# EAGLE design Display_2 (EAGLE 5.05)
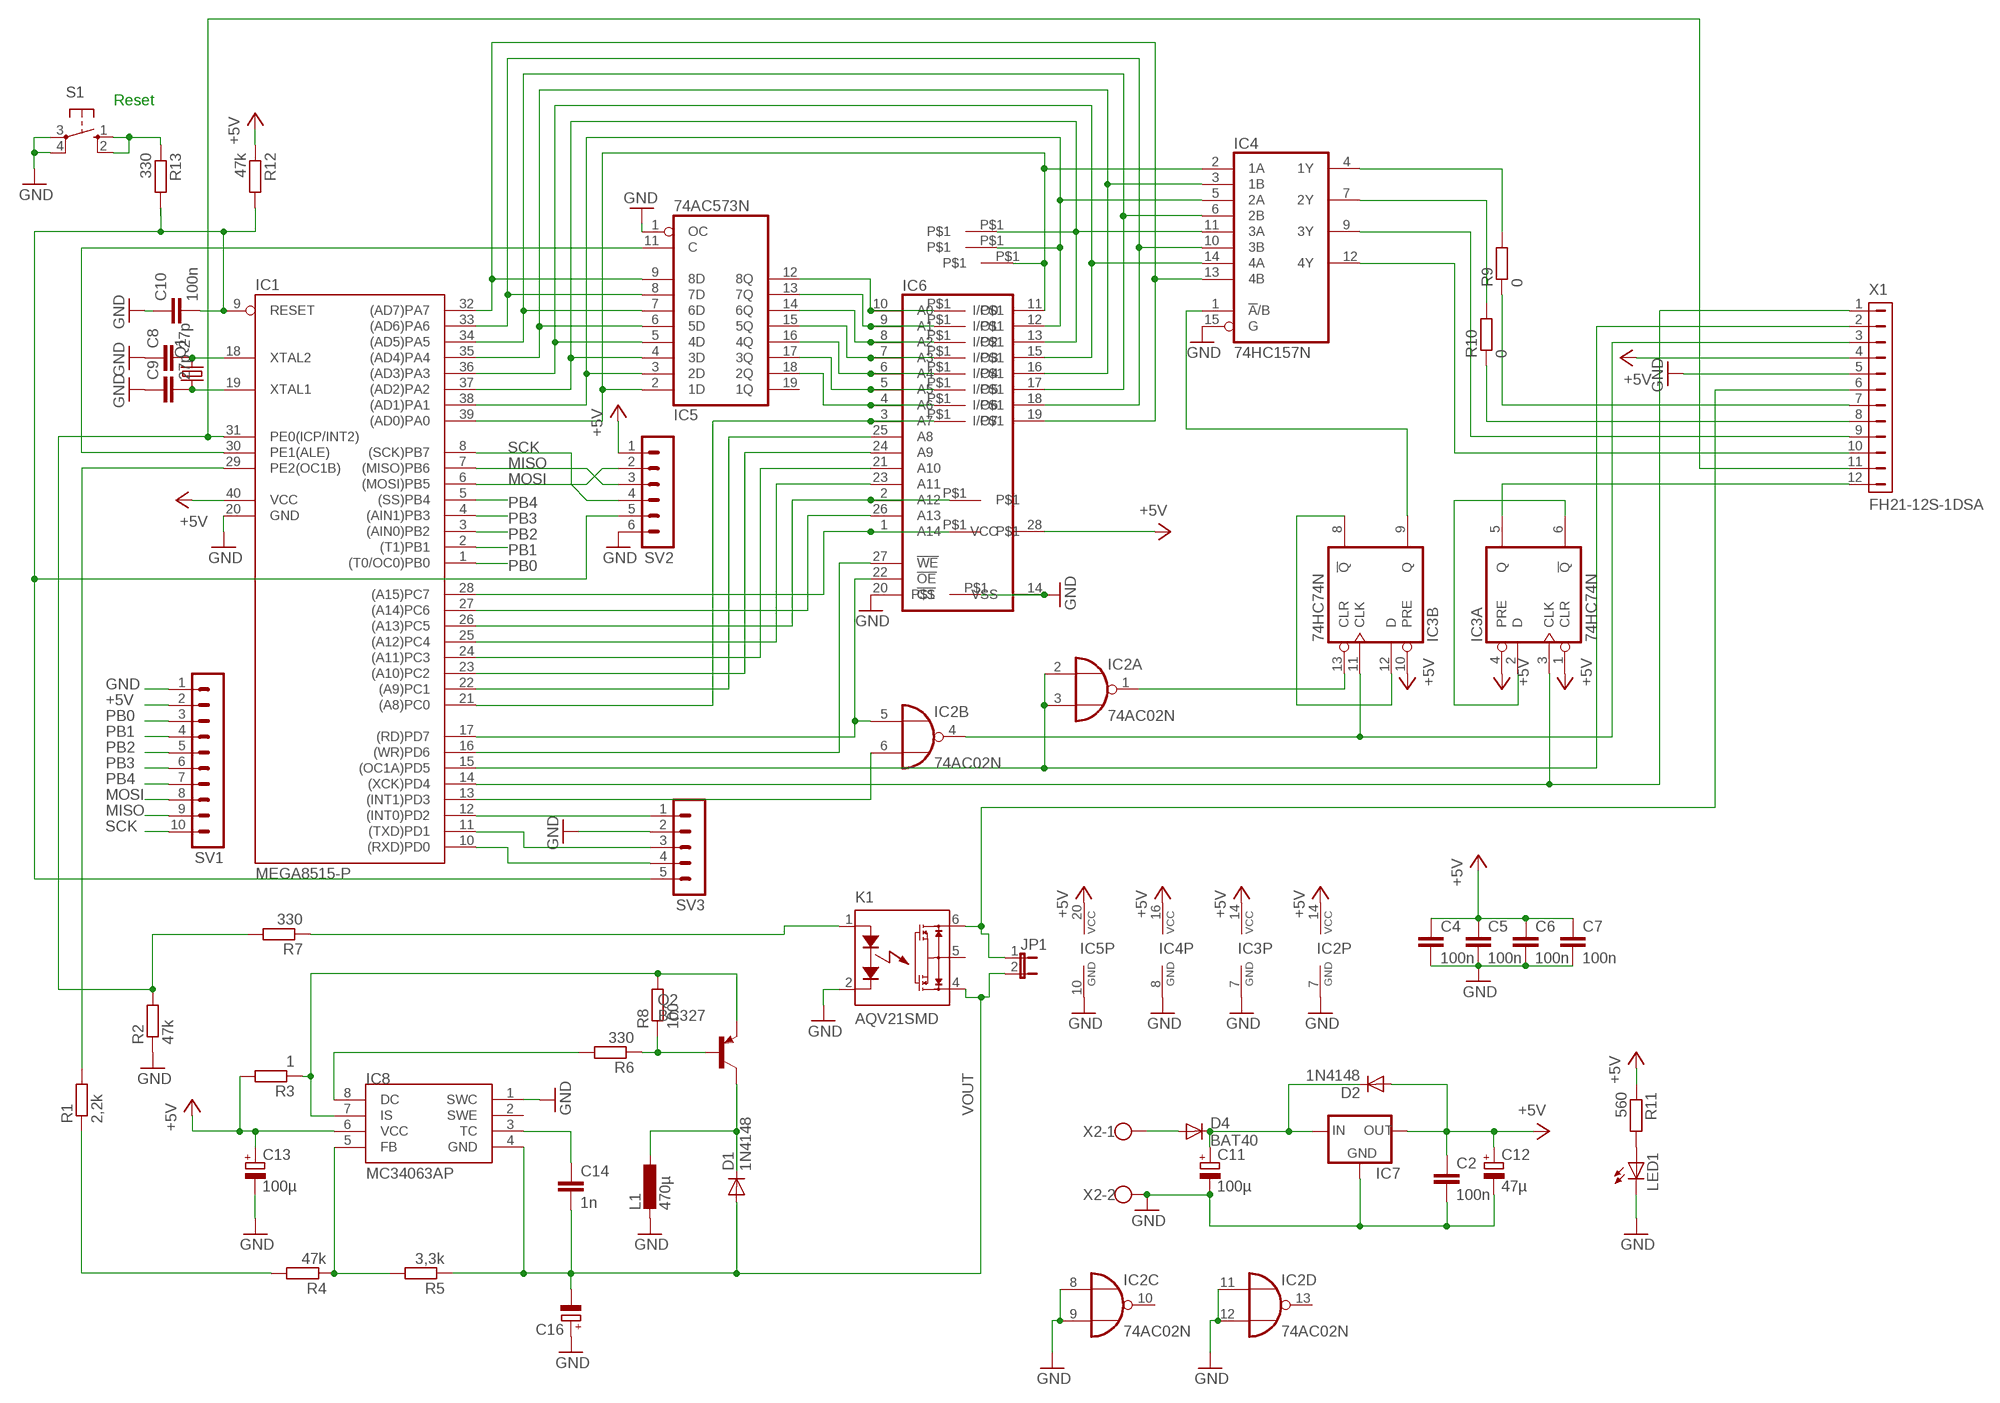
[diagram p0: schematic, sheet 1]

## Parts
C2  100n  C-EUC1206  [C1206]
C4  100n  C-EUC1206  [C1206]
C5  100n  C-EUC1206  [C1206]
C6  100n  C-EUC1206  [C1206]
C7  100n  C-EUC1206  [C1206]
C8  27p  C-EUC1206  [C1206]
C9  27p  C-EUC1206  [C1206]
C10  100n  C-EUC1206  [C1206]
C11  100µ  CPOL-EUE5-5  [E5-5]
C12  47µ  CPOL-EUE5-5  [E5-5]
C13  100µ  CPOL-EUE5-5  [E5-5]
C14  1n  C-EUC1206  [C1206]
C16  CPOL-EUE5-5  [E5-5]
D1  1N4148  DIODE-D-2.5  [D-2.5]
D2  1N4148  [DO35-10]
D4  BAT40  DIODE-D-2.5  [D-2.5]
IC1  MEGA8515-P  [DIL40]
IC2  74AC02N  [DIL14]
IC3  74HC74N  [DIL14]
IC4  74HC157N  [DIL16]
IC5  74AC573N  [DIL20]
IC6  62256P  [DIL28-6]
IC7  78XXS  [78XXS]
IC8  MC34063AP  [DIL08]
JP1  JP1E  [JP1]
K1  AQV21SMD  [DIL06SMD]
L1  470µ  L-EU0204/7  [0204/7]
LED1  LED3MM  [LED3MM]
Q1  CRYSTALHC49U-V  [HC49U-V]
Q2  BC327  [TO92]
R1  2,2k  R-EU_M1206  [M1206]
R2  47k  R-EU_M1206  [M1206]
R3  1  R-EU_M1206  [M1206]
R4  47k  R-EU_M1206  [M1206]
R5  3,3k  R-EU_M1206  [M1206]
R6  330  R-EU_M1206  [M1206]
R7  330  R-EU_M1206  [M1206]
R8  100  R-EU_M1206  [M1206]
R9  0  R-EU_0207/10  [0207/10]
R10  0  R-EU_0207/10  [0207/10]
R11  560  R-EU_M1206  [M1206]
R12  47k  R-EU_M1206  [M1206]
R13  330  R-EU_M1206  [M1206]
S1  10-XX  [B3F-10XX]
SV1  MA10-1  [MA10-1]
SV2  MA06-1  [MA06-1]
SV3  MA05-1  [MA05-1]
U$2  PAD  [PAD]
U$3  PAD  [PAD]
U$4  PAD  [PAD]
U$5  PAD  [PAD]
U$6  PAD  [PAD]
U$7  PAD  [PAD]
U$8  PAD  [PAD]
U$9  PAD  [PAD]
U$10  PAD  [PAD]
U$11  PAD  [PAD]
U$12  PAD  [PAD]
U$13  PAD  [PAD]
U$14  PAD  [PAD]
U$15  PAD  [PAD]
X1  FH21-12S-1DSA  [FH21-12S-1DSA]
X2  W237-102  [W237-102]

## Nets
+5V [Power]: C2.1 C4.1 C5.1 C6.1 C7.1 C12.+ C13.+ D2.A IC1.40(VCC) IC2.14(P:VCC) IC3.1(A:CLR) IC3.4(A:PRE) IC3.10(B:PRE) IC3.14(P:VCC) IC4.16(VCC) IC5.20(VCC) IC6.28(VCC) IC7.OUT IC8.6(VCC) R3.2 R11.1 R12.1 SV1.2 SV2.1 X1.4
GND: C2.2 C4.2 C5.2 C6.2 C7.2 C8.1 C9.1 C10.1 C11.- C12.- C13.- C16.+ IC1.20(GND) IC2.7(P:GND) IC2.8(C:I0) IC2.9(C:I1) IC2.11(D:I0) IC2.12(D:I1) IC3.7(P:GND) IC4.8(GND) IC4.15(G) IC5.1(OC) IC5.10(GND) IC6.14(VSS) IC6.20(!CS) IC7.GND IC8.1(SWC) K1.2(K) L1.2 LED1.K(C) R2.1 S1.3(P) S1.4(P1) SV1.1 SV2.6 SV3.2 U$11.P$1 X1.5 X2.2
L1 [Power]: D1.C L1.1 Q2.3(C)
MISO: IC1.7((MISO)PB6) SV1.9 SV2.3
MOSI: IC1.6((MOSI)PB5) SV1.8 SV2.2
N$1: IC1.39((AD0)PA0) IC4.2(1A) IC5.2(1D) IC6.11(I/O0) U$15.P$1
N$2: IC1.38((AD1)PA1) IC4.5(2A) IC5.3(2D) IC6.12(I/O1) U$13.P$1
N$3: IC1.37((AD2)PA2) IC4.11(3A) IC5.4(3D) IC6.13(I/O2) U$8.P$1
N$4: IC1.36((AD3)PA3) IC4.14(4A) IC5.5(4D) IC6.15(I/O3)
N$5: IC1.35((AD4)PA4) IC4.3(1B) IC5.6(5D) IC6.16(I/O4)
N$6: IC1.34((AD5)PA5) IC4.6(2B) IC5.7(6D) IC6.17(I/O5)
N$7: IC1.33((AD6)PA6) IC4.10(3B) IC5.8(7D) IC6.18(I/O6)
N$8: IC1.32((AD7)PA7) IC4.13(4B) IC5.9(8D) IC6.19(I/O7)
N$9: IC5.12(8Q) IC6.10(A0) U$4.P$1
N$10: IC5.13(7Q) IC6.9(A1) U$5.P$1
N$11: IC5.14(6Q) IC6.8(A2) U$6.P$1
N$12: IC5.15(5Q) IC6.7(A3) U$12.P$1
N$13: IC5.16(4Q) IC6.6(A4) U$14.P$1
N$14: IC5.17(3Q) IC6.5(A5) U$7.P$1
N$15: IC5.18(2Q) IC6.4(A6) U$9.P$1
N$16: IC1.21((A8)PC0) IC6.3(A7) U$10.P$1
N$17: IC1.22((A9)PC1) IC6.25(A8)
N$18: IC1.23((A10)PC2) IC6.24(A9)
N$19: IC1.24((A11)PC3) IC6.21(A10)
N$20: IC1.25((A12)PC4) IC6.23(A11)
N$21: IC1.26((A13)PC5) IC6.2(A12) U$3.P$1
N$22: IC1.27((A14)PC6) IC6.26(A13)
N$23: IC1.28((A15)PC7) IC6.1(A14) U$2.P$1
N$24: IC1.16((WR)PD6) IC6.27(!WE)
N$25: IC1.17((RD)PD7) IC2.5(B:I0) IC6.22(!OE)
N$26: IC3.8(B:!Q) IC3.12(B:D)
N$27: IC3.9(B:Q) IC4.1(!A!/B)
N$28: IC3.2(A:D) IC3.6(A:!Q)
N$29: IC2.1(A:O) IC3.13(B:CLR)
N$31: IC1.13((INT1)PD3) IC2.6(B:I1)
N$32: C8.2 IC1.18(XTAL2) Q1.2
N$33: C9.2 IC1.19(XTAL1) Q1.1
N$34: R13.1 S1.1(S) S1.2(S1)
N$35: IC1.31(PE0(ICP/INT2)) R2.2 R7.2 X1.11
N$36: IC1.15((OC1A)PD5) IC2.2(A:I0) IC2.3(A:I1) X1.2
N$37: IC1.30(PE1(ALE)) IC5.11(C)
N$38: IC3.5(A:Q) X1.12
N$39: IC2.4(B:O) IC3.11(B:CLK) X1.3
N$40: R9.1 X1.7
N$41: R10.1 X1.8
N$42: IC4.9(3Y) X1.9
N$43: IC4.12(4Y) X1.10
N$45: C14.1 IC8.3(TC)
N$48: IC8.5(FB) R4.1 R5.2
N$49: K1.1(A) R7.1
N$50: LED1.A R11.2
N$51: R1.1 R4.2
N$52: IC1.29(PE2(OC1B)) R1.2
N$53: IC8.8(DC) R6.2
N$54: Q2.2(B) R6.1 R8.1
N$55: IC8.7(IS) Q2.1(E) R3.1 R8.2
N$57 [Power]: JP1.1 K1.6(D1) X1.6
N$58: IC4.4(1Y) R9.2
N$59: IC4.7(2Y) R10.2
N$60: D4.A X2.1
N$61: IC1.14((XCK)PD4) IC3.3(A:CLK) X1.1
N$63: IC1.12((INT0)PD2) SV3.1
PB0: IC1.1((T0/OC0)PB0) SV1.3
PB1: IC1.2((T1)PB1) SV1.4
PB2: IC1.3((AIN0)PB2) SV1.5
PB3: IC1.4((AIN1)PB3) SV1.6
PB4: IC1.5((SS)PB4) SV1.7
RESET: C10.2 IC1.9(RESET) R12.2 R13.2 SV2.5 SV3.5
RXD: IC1.10((RXD)PD0) SV3.4
SCK: IC1.8((SCK)PB7) SV1.10 SV2.4
TXD: IC1.11((TXD)PD1) SV3.3
VIN: C11.+ D2.C D4.C IC7.IN
VOUT [Power]: C14.2 C16.- D1.A IC8.4(GND) JP1.2 K1.4(D2) R5.1
Unconnected: IC2.10(C:O) IC2.13(D:O) IC5.19(1Q) IC8.2(SWE) K1.5(S)

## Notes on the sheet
- Reset

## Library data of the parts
C2 C4-C10 C14 = rcl:C-EU: CAPACITOR, European symbol
C11-C13 C16 = rcl:CPOL-EU: POLARIZED CAPACITOR, European symbol
D1 D4 = diode:DIODE-: DIODE
D2 = diode:1N4148: DIODE
IC1 = atmel:MEGA8515-P: MICROCONTROLLER 8 Kbytes FLASH 512 bytes SRAM 512 bytes EEPROM USART 8-channel 10 bit ADC Source: avr.lbr
IC2 = 74xx-eu:74*02: Quad 2-input NOR gate
IC3 = 74xx-eu:74*74: Dual D type positive edge triggered FLIP FLOP, preset and clear
IC4 = 74xx-eu:74*157: Quadruple 2-line to 1-line data SELECTOR/MULTIPLEXER
IC5 = 74xx-eu:74*573: 8-bit D latch BUS DRIVER
IC6 = memory-hitachi:62256P: MEMORY
IC7 = v-reg:78XXS: VOLTAGE REGULATOR
IC8 = mc34063:MC34063
JP1 = jumper:JP1E: JUMPER
K1 = relay:AQV*: PhotoMOS Relay NAiS Source: http://www.mew-europe.com/.. pti_en.pdf
L1 = rcl:L-EU: INDUCTOR, European symbol
LED1 = led:LED: LED
Q1 = crystal:CRYSTAL: CRYSTAL
Q2 = transistor-pnp:BC327: PNP Transistor
R1-R13 = rcl:R-EU_: RESISTOR, European symbol
S1 = switch-omron:10-XX: OMRON SWITCH
SV1 = con-lstb:MA10-1: PIN HEADER
SV2 = con-lstb:MA06-1: PIN HEADER
SV3 = con-lstb:MA05-1: PIN HEADER
U$2-U$15 = special-pad:PAD
X1 = con-hirose:FH21-12S-1DSA: FPC CONNECTOR Source: con-hirose.lbr from Bob Starr <rtzaudio@mindspring.com>
X2 = con-wago-500:W237-102: WAGO SCREW CLAMP

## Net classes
0 default: width 0.4 mm
1 Power: width 0.6 mm
2 Supply: width 1 mm

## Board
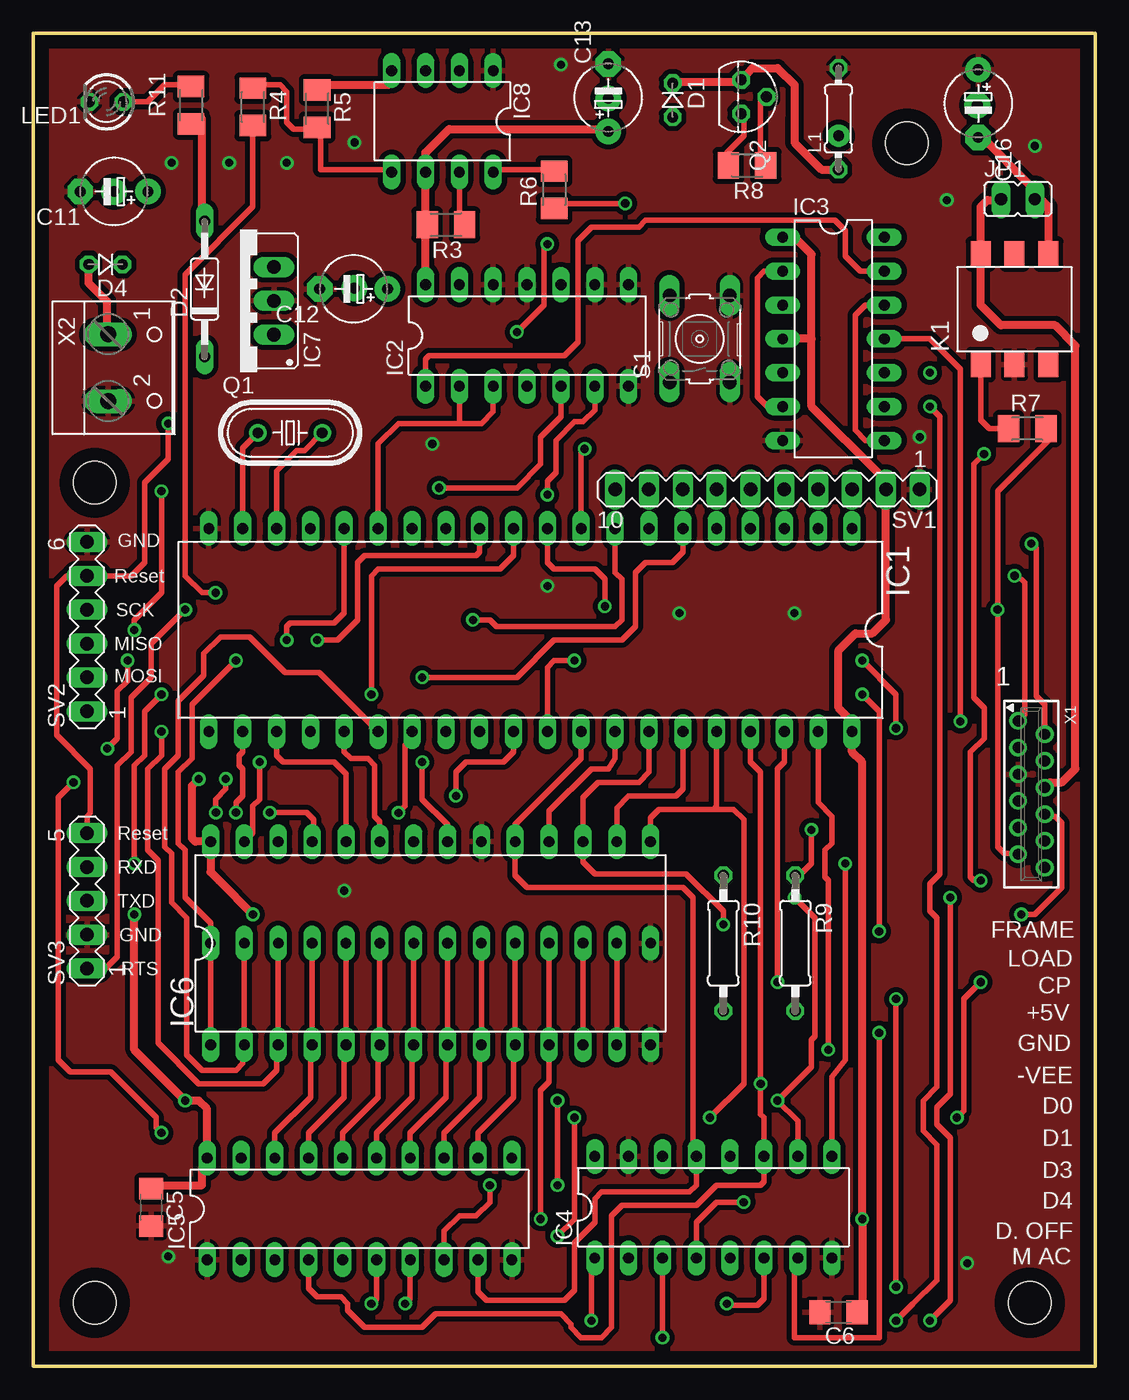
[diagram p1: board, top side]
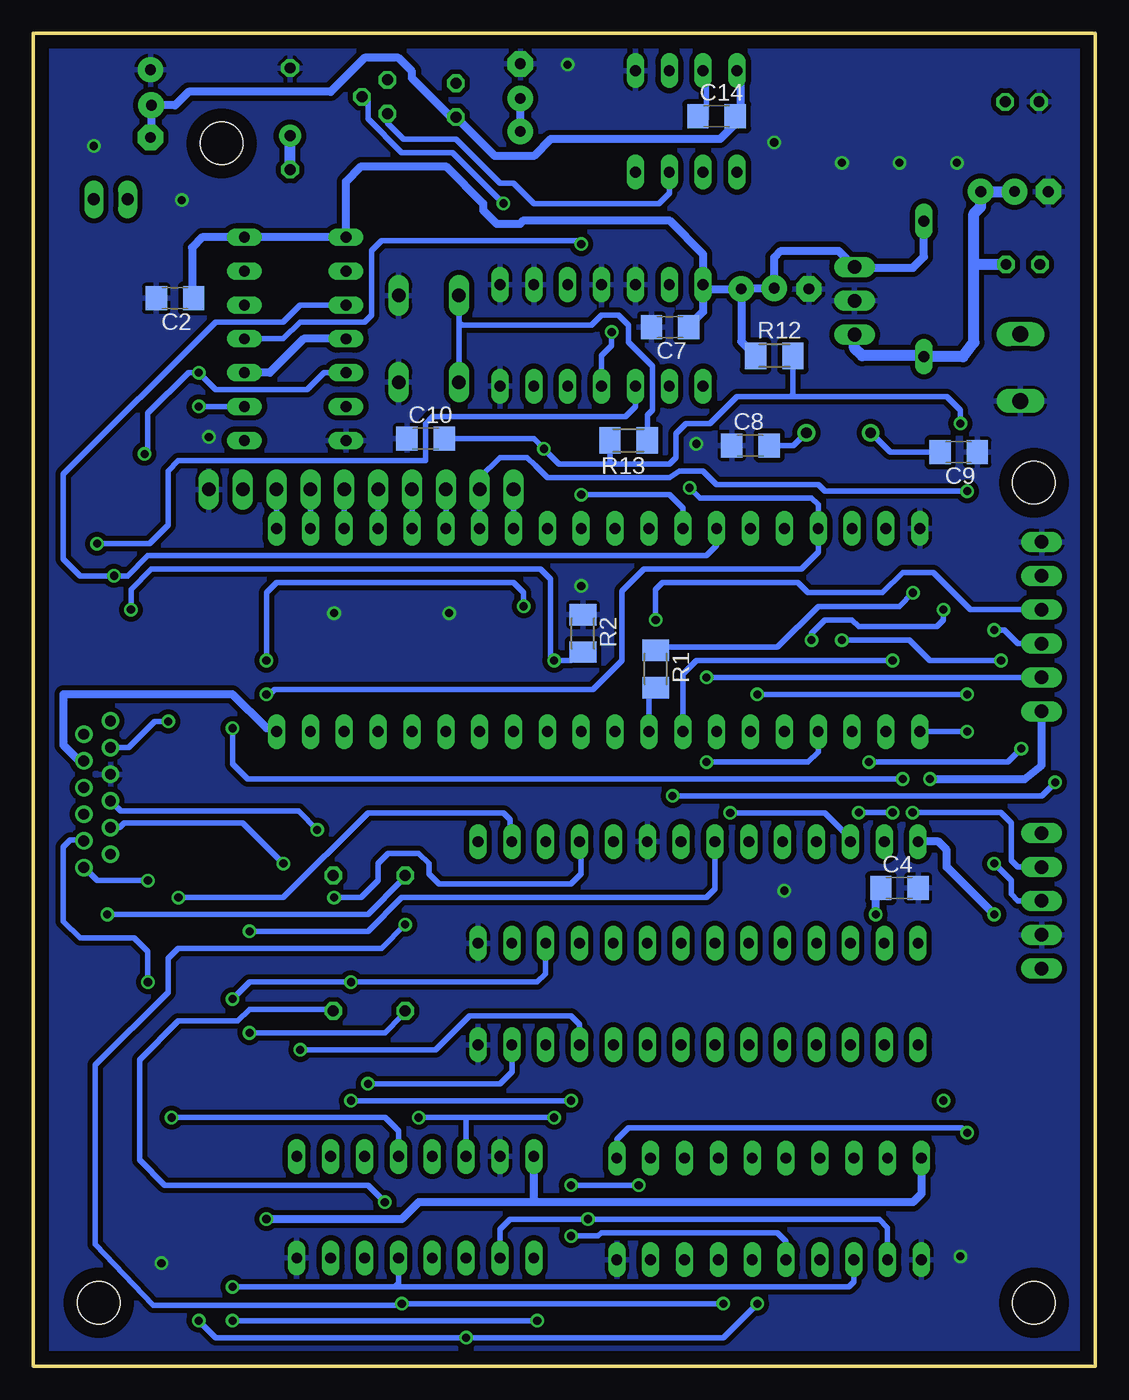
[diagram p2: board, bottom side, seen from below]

Size 79.68 x 100 mm. Coordinates in mm from the lower left corner, seen from the top.
Outline: 79.68,99.99 79.68,0 0,0 0,99.99
Outline: 0.15,100 79.53,100
Copper layers (1*16): Top 0.035mm / dielectric 1.5mm / Bottom 0.035mm
Design rules "Bilex_DRU_15mil": minimum track width 10mil, minimum drill 24mil, track to track 15mil, track to pad 15mil, pad to pad 15mil, via to via 15mil, smd to smd 10mil, copper to edge 40mil, drill to drill 8mil, minimum pad ring 10mil, minimum via ring 8mil, stop-mask expansion 4mil, vias tented up to drill 0mil, thermal gap 10mil
Holes 3.2 mm at 4.6,4.75 4.6,66.28 74.77,4.75 65.56,91.74

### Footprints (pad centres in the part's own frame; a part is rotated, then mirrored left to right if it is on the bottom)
C1206 = smd 1.6 x 1.8: 1 -1.4,0; 2 1.4,0
E5-5 = drill 0.813 pad 1.905 round: + -2.54,0 | drill 0.813 pad 1.905 octagon: - 2.54,0
D-2.5 = drill 0.813 octagon: A 1.27,0; C -1.27,0
DO35-10 = drill 0.813 long: A 5.08,0; C -5.08,0
DIL40 = drill 0.813 long: 1 -24.13,-7.62; 2 -21.59,-7.62; 3 -19.05,-7.62; 4 -16.51,-7.62; 5 -13.97,-7.62; 6 -11.43,-7.62; 7 -8.89,-7.62; 8 -6.35,-7.62; 9 -3.81,-7.62; 10 -1.27,-7.62; 11 1.27,-7.62; 12 3.81,-7.62; 13 6.35,-7.62; 14 8.89,-7.62; 15 11.43,-7.62; 16 13.97,-7.62; 17 16.51,-7.62; 18 19.05,-7.62; 19 21.59,-7.62; 20 24.13,-7.62; 21 24.13,7.62; 22 21.59,7.62; 23 19.05,7.62; 24 16.51,7.62; 25 13.97,7.62; 26 11.43,7.62; 27 8.89,7.62; 28 6.35,7.62; 29 3.81,7.62; 30 1.27,7.62; 31 -1.27,7.62; 32 -3.81,7.62; 33 -6.35,7.62; 34 -8.89,7.62; 35 -11.43,7.62; 36 -13.97,7.62; 37 -16.51,7.62; 38 -19.05,7.62; 39 -21.59,7.62; 40 -24.13,7.62
DIL14 = drill 0.813 long: 1 -7.62,-3.81; 2 -5.08,-3.81; 3 -2.54,-3.81; 4 0,-3.81; 5 2.54,-3.81; 6 5.08,-3.81; 7 7.62,-3.81; 8 7.62,3.81; 9 5.08,3.81; 10 2.54,3.81; 11 0,3.81; 12 -2.54,3.81; 13 -5.08,3.81; 14 -7.62,3.81
DIL16 = drill 0.813 long: 1 -8.89,-3.81; 2 -6.35,-3.81; 3 -3.81,-3.81; 4 -1.27,-3.81; 5 1.27,-3.81; 6 3.81,-3.81; 7 6.35,-3.81; 8 8.89,-3.81; 9 8.89,3.81; 10 6.35,3.81; 11 3.81,3.81; 12 1.27,3.81; 13 -1.27,3.81; 14 -3.81,3.81; 15 -6.35,3.81; 16 -8.89,3.81
DIL20 = drill 0.813 long: 1 -11.43,-3.81; 2 -8.89,-3.81; 3 -6.35,-3.81; 4 -3.81,-3.81; 5 -1.27,-3.81; 6 1.27,-3.81; 7 3.81,-3.81; 8 6.35,-3.81; 9 8.89,-3.81; 10 11.43,-3.81; 11 11.43,3.81; 12 8.89,3.81; 13 6.35,3.81; 14 3.81,3.81; 15 1.27,3.81; 16 -1.27,3.81; 17 -3.81,3.81; 18 -6.35,3.81; 19 -8.89,3.81; 20 -11.43,3.81
DIL28-6 = drill 0.813 long: 1 -16.51,-7.62; 2 -13.97,-7.62; 3 -11.43,-7.62; 4 -8.89,-7.62; 5 -6.35,-7.62; 6 -3.81,-7.62; 7 -1.27,-7.62; 8 1.27,-7.62; 9 3.81,-7.62; 10 6.35,-7.62; 11 8.89,-7.62; 12 11.43,-7.62; 13 13.97,-7.62; 14 16.51,-7.62; 15 16.51,7.62; 16 13.97,7.62; 17 11.43,7.62; 18 8.89,7.62; 19 6.35,7.62; 20 3.81,7.62; 21 1.27,7.62; 22 -1.27,7.62; 23 -3.81,7.62; 24 -6.35,7.62; 25 -8.89,7.62; 26 -11.43,7.62; 27 -13.97,7.62; 28 -16.51,7.62
78XXS = drill 1.016 long: GND 0,-2.54; IN -2.54,-2.54; OUT 2.54,-2.54
DIL08 = drill 0.813 long: 1 -3.81,-3.81; 2 -1.27,-3.81; 3 1.27,-3.81; 4 3.81,-3.81; 5 3.81,3.81; 6 1.27,3.81; 7 -1.27,3.81; 8 -3.81,3.81
JP1 = drill 0.914 long: 1 0,-1.27; 2 0,1.27
DIL06SMD = smd 1.5 x 1.9: 1 -2.54,-4.15; 2 0,-4.15; 3 2.54,-4.15; 4 2.54,4.15; 5 0,4.15; 6 -2.54,4.15
0204/7 = drill 0.813 octagon: 1 -3.81,0; 2 3.81,0
LED3MM = drill 0.813 octagon: A -1.27,0; K 1.27,0
HC49U-V = drill 0.813 round: 1 -2.413,0; 2 2.413,0
TO92 = drill 0.813 octagon: 1 1.27,0; 2 0,1.905; 3 -1.27,0
M1206 = smd 1.6 x 2: 1 -1.4,0; 2 1.4,0
0207/10 = drill 0.813 octagon: 1 -5.08,0; 2 5.08,0
B3F-10XX = drill 1.016 long: 1 -3.251,2.261; 2 3.251,2.261; 3 -3.251,-2.261; 4 3.251,-2.261
MA10-1 = drill 1.016 long: 1 -11.43,0; 2 -8.89,0; 3 -6.35,0; 4 -3.81,0; 5 -1.27,0; 6 1.27,0; 7 3.81,0; 8 6.35,0; 9 8.89,0; 10 11.43,0
MA06-1 = drill 1.016 long: 1 -6.35,0; 2 -3.81,0; 3 -1.27,0; 4 1.27,0; 5 3.81,0; 6 6.35,0
MA05-1 = drill 1.016 long: 1 -5.08,0; 2 -2.54,0; 3 0,0; 4 2.54,0; 5 5.08,0
PAD = drill 0.8 long: P$1 0,0
FH21-12S-1DSA = drill 0.813 round: 1 -5.5,-1; 2 -4.5,1; 3 -3.5,-1; 4 -2.5,1; 5 -1.5,-1; 6 -0.5,1; 7 0.5,-1; 8 1.5,1; 9 2.5,-1; 10 3.5,1; 11 4.5,-1; 12 5.5,1
W237-102 = drill 1.194 long: 1 -2.5,-1.27; 2 2.5,-1.27

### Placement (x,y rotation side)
C2  69.05,80.12 180 bottom
C4  14.69,35.86 0 bottom
C5  8.85,11.92 270 top
C6  60.41,4.05 180 top
C7  31.9,77.96 180 bottom
C8  25.87,69.07 0 bottom
C9  10.25,68.56 180 bottom
C10  50.25,69.58 0 bottom
C11  6.06,88.12 180 top
C12  24.03,80.82 180 top
C13  43.14,95.17 90 top
C14  28.41,93.77 0 bottom
C16  70.89,94.73 270 top
D1  47.97,94.98 270 top
D2  12.85,80.82 90 top
D4  5.42,82.66 180 top
IC1  37.3,55.23 180 top
IC2  37.05,77.33 0 top
IC3  60.03,77.07 270 top
IC4  51.02,11.92 0 top
IC5  24.47,11.8 0 top
IC6  29.81,31.73 0 top
IC7  15.52,79.93 90 top
IC8  30.7,93.39 180 top
JP1  73.88,87.55 270 top
K1  73.62,79.3 0 top
L1  60.41,93.58 90 top
LED1  5.49,94.85 180 top
Q1  19.27,70.03 0 top
Q2  53.11,95.23 270 top
R1  32.98,52.31 270 bottom
R2  38.44,54.98 270 bottom
R3  30.95,85.65 180 top
R4  16.47,94.47 270 top
R5  21.3,94.35 270 top
R6  39.08,88.25 90 top
R7  74.57,70.34 0 top
R8  53.56,90.09 180 top
R9  57.18,31.73 270 top
R10  51.78,31.73 270 top
R11  11.84,94.6 90 top
R12  24.09,75.8 0 bottom
R13  35.01,69.45 180 bottom
S1  50,77.07 90 top
SV1  55.08,65.77 180 top
SV2  4.03,55.48 90 top
SV3  4.03,34.91 90 top
U$2  13.3,31.73 270 top
U$3  15.84,31.73 270 top
U$4  36.16,31.73 270 top
U$5  33.62,31.73 270 top
U$6  31.08,31.73 270 top
U$7  23.46,31.73 270 top
U$8  43.78,31.73 270 top
U$9  20.92,31.73 270 top
U$10  18.38,31.73 270 top
U$11  46.32,31.73 270 top
U$12  28.54,31.73 270 top
U$13  41.24,31.73 270 top
U$14  26,31.73 270 top
U$15  38.7,31.73 270 top
X1  74.89,42.91 270 top
X2  6.88,74.92 270 top

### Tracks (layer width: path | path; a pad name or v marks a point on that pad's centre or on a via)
+5V  (via drill 0.61, 0.8 pad 1.93)
  Top 0.6: 13.93,36.43 v16.47,33.89 | C5.1 8.85,13.57 12.66,13.57 12.66,14.84 IC5.20 | v7.58,33.89 7.58,23.73 v11.39,19.92 | 62.19,45.32 v62.19,11.03 62.19,4.68 C6.1 | 29.17,85.96 R3.2 29.43,85.71 29.17,85.46 29.43,85.2 IC2.14 | IC3.1 57.11,84.69 58.38,83.42 58.38,77.07 58.38,71.99 63.46,66.91 | 57.11,77.07 IC3.4 | R11.1 12.66,93.58 12.66,85.96 D2.A
  Top 0.61: v11.39,19.92 12.41,19.92 13.04,19.29 IC5.20 | 63.46,66.91 63.97,66.41 SV1.2 63.97,55.99 62.95,54.98 61.68,54.98 60.41,53.71 60.41,49.39 61.43,48.37 IC1.40 61.43,46.09 62.19,45.32 | 58.38,77.07 57.11,77.07 | C13.+ 42.95,92.63 42.89,92.82 31.2,92.82 29.43,91.04 IC8.6 29.43,85.77 R3.2 | 13.93,36.43 13.3,37.07 IC6.28 12.15,39.35 11.9,39.61 11.9,43.55 v12.41,44.05
  Bottom 0.6: v16.47,33.89 16.47,35.16 C4.1 | 62.19,47.86 64.73,50.4 77.43,50.4 77.43,46.59 76.16,45.32 X1.4 | C7.1 30.44,78.34 | IC3.1 IC3.14 | IC3.10 61.94,74.53 59.4,77.07 IC3.4 | 15.2,12.3 41.87,12.3 50.76,12.3 52.03,11.03 v62.19,11.03
  Bottom 0.61: v12.41,44.05 5.3,44.05 4.03,45.07 SV2.1 | C13.+ v43.14,95.11 | D2.A 12.85,83.23 13.68,82.41 18,82.41 | IC2.14 29.43,79.11 30.44,78.09 30.44,78.02 C7.1 | IC2.14 29.43,83.42 31.97,85.96 42.89,85.96 43.14,85.71 44.92,85.71 45.94,86.73 45.94,87.23 48.73,90.03 55.08,90.03 56.22,88.89 IC3.1 | 62.19,47.86 61.68,47.86 IC1.40 | IC4.16 42.13,12.56 41.87,12.3 | IC7.OUT 19.27,83.68 23.58,83.68 24.09,83.17 v24.09,80.88 26.5,80.88 C12.+ | C12.+ 29.11,80.82 IC2.14 | C12.+ 26.57,76.88 R12.1 | IC3.14 67.02,84.69 67.78,83.93 67.78,80.25 C2.1 | 15.2,12.3 13.68,12.3 13.04,12.94 IC5.20 | IC6.28 11.77,39.35 11.14,38.72 11.14,37.45 v7.58,33.89
  Bottom 0.813: IC7.OUT 18,82.41
GND  (via drill 0.61)
  other vias: 29.93,69.2 10.12,8.24 70.07,7.73 23.33,35.67 38.57,58.53 48.48,56.5 57.11,56.5 66.51,69.71 68.54,87.49 75.15,91.55 39.59,97.65 10.38,90.28 14.69,90.28 19.01,90.28 24.09,91.81
  pour Bottom: 0.98,99.17 78.7,99.17 78.7,0.75 0.85,0.75 0.85,99.43
  pour Top: 0.98,99.3 78.7,99.3 78.7,0.87 0.98,0.87 0.98,99.17
L1  (via drill 0.8 pad 1.68)
  Top 0.6: 53.05,96.38 47.97,96.38 D1.C | 57.11,93.58 57.11,96.12 55.84,97.39 53.94,97.39 53.05,96.38 | 53.05,96.38 Q2.3
  Top 0.61: 57.11,93.58 57.11,91.81 59.14,89.77 L1.1
  Bottom 0.813: L1.1 v60.41,92.31
MISO  (via drill 0.61)
  Top 0.406: v7.58,55.23 7.58,55.99 9.61,58.02 v9.61,65.64
  Bottom 0.4: SV2.3 5.8,54.21 6.82,55.23 v7.58,55.23
  Bottom 0.406: v9.61,65.64 20.28,65.64 20.79,66.15 28.41,66.15 29.43,67.17 31.2,67.17 31.97,66.66 41.11,66.66 42,67.55 | IC1.7 SV1.9 46.19,66.66 44.67,68.18 42.63,68.18 42,67.55 | 42,67.55 41.62,67.17
MOSI  (via drill 0.61)
  Top 0.406: v29.17,51.67 36.28,51.67 39.08,54.47 44.16,54.47 45.17,55.48 45.17,59.55 45.94,60.31 47.97,60.31 48.73,61.07 IC1.6
  Bottom 0.4: SV2.2 v29.17,51.67
  Bottom 0.406: IC1.6 SV1.8
N$1  (via drill 0.61)
  Top 0.406: v59.65,23.73 59.65,36.43 59.4,36.69 59.4,38.72 59.91,39.23 59.91,41.26 58.89,42.28 IC1.39 | U$15.P$1 IC6.11 38.7,21.32 38.06,20.69 v38.06,11.03
  Bottom 0.4: 41.87,11.03 v38.06,11.03 18.25,11.03 17.74,11.03 | v59.65,23.73 49.49,23.73 46.95,26.27 40.6,26.27
  Bottom 0.406: IC6.11 38.7,25.64 39.33,26.27 40.6,26.27 | IC5.2 15.58,10.4 16.22,11.03 18.25,11.03 | IC4.2 44.67,10.27 43.9,11.03 41.87,11.03
N$2  (via drill 0.61)
  Top 0.4: v64.73,5.95 v64.73,27.54
  Top 0.406: v55.84,28.81 55.84,44.82 56.35,45.32 IC1.38 | U$13.P$1 IC6.12
  Bottom 0.4: 19.01,5.95 50.76,5.95 | 44.41,28.81 45.43,28.81 v55.84,28.81 63.46,28.81 v64.73,27.54 | 53.3,5.95 v64.73,5.95
  Bottom 0.406: U$13.P$1 41.24,29.45 41.87,28.81 45.43,28.81 | IC5.3 18.12,6.33 18.5,5.95 19.01,5.95 | 50.76,5.95 52.54,5.95 | 52.54,5.95 53.3,5.95 | IC4.5 52.29,6.21 52.54,5.95
N$3  (via drill 0.61)
  Top 0.4: v54.57,21.19 54.57,18.91 54.83,18.65 IC4.11
  Top 0.406: IC6.13 U$8.P$1 | IC5.4 20.66,5.83 21.3,5.19 23.08,5.19 23.58,4.68 23.58,4.18 24.85,2.91 29.17,2.91 30.19,3.92 39.59,3.92 40.35,3.16 40.35,2.91 41.11,2.14 42.63,2.14 43.4,2.91 43.4,11.29 44.16,12.05 49.75,12.05 51.27,13.57 54.57,13.57 54.83,13.83 IC4.11 | v54.57,21.19 54.57,44.56 53.81,45.32 IC1.37
  Bottom 0.406: IC6.13 43.78,22.08 44.67,21.19 v54.57,21.19
N$4  (via drill 0.61)
  Top 0.4: v39.33,9.76 40.6,11.03 v40.6,18.65 | 53.3,32.62 53.3,21.19 v50.76,18.65
  Top 0.406: IC6.15 46.32,41.13 46.95,41.77 51.02,41.77 | 53.3,32.62 53.3,41.01 52.54,41.77 51.02,41.77 | IC1.36 51.27,42.02 51.02,41.77
  Bottom 0.4: 24.35,10.02 37.05,10.02 37.3,9.76 v39.33,9.76 | v40.6,18.65 47.21,18.65 v50.76,18.65
  Bottom 0.406: 47.21,18.65 IC4.14 | IC5.5 23.2,9.38 23.84,10.02 24.35,10.02
N$5  (via drill 0.61)
  Top 0.406: v47.21,2.14 IC4.3 | v68.8,35.16 68.8,20.43 67.78,19.42 67.78,18.15 68.8,17.13 68.8,4.94 v67.27,3.41 | IC1.35 48.73,43.29 48.22,42.78 44.67,42.78 43.78,41.89 IC6.16 | IC5.6 25.74,5.07 v25.36,4.68
  Bottom 0.4: v25.36,4.68 27.9,2.14 v47.21,2.14 66,2.14 v67.27,3.41 | 45.68,41.51 54.57,41.51 60.92,35.16 v68.8,35.16
  Bottom 0.406: 45.68,41.51 44.41,41.51 43.9,41.01 43.9,39.48 IC6.16
N$6  (via drill 0.61)
  Top 0.406: IC1.34 46.19,44.56 45.43,43.8 42.38,43.8 41.75,43.16 | 41.75,43.16 41.36,42.78 | IC4.6 54.83,5.07 54.32,4.56 52.16,4.56 v52.03,4.68 | v51.78,33.13 51.78,34.15 48.98,36.94 42.13,36.94 41.62,37.45 | 41.62,37.45 41.36,37.7 | IC5.7 28.28,5.07 v27.9,4.68 | 41.75,43.16 41.24,42.66 IC6.17 41.24,37.83 41.62,37.45
  Bottom 0.4: v27.9,4.68 v52.03,4.68
  Bottom 0.406: v52.03,4.68 52.16,4.56 70.7,4.56 75.02,9.13 75.02,22.59 69.56,28.05 69.56,30.59 68.8,31.35 53.56,31.35 v51.78,33.13
N$7  (via drill 0.61)
  Top 0.4: 34.25,12.3 v34.25,13.57 | v39.33,13.57 v39.33,19.92 | IC4.10 57.37,18.4 v55.84,19.92 58.38,22.46 58.38,24.5 58.64,24.75 58.64,33.64 v57.11,35.16
  Top 0.406: IC1.33 43.65,45.58 43.14,44.82 41.87,44.82 38.7,41.64 IC6.18 | IC5.8 30.82,10.14 31.97,11.29 33.24,11.29 34.25,12.3
  Bottom 0.4: v34.25,13.57 v39.33,13.57 | v39.33,19.92 v55.84,19.92
  Bottom 0.406: v57.11,35.16 55.08,35.16 53.81,36.43 53.81,37.7 53.05,38.47 50.76,38.47 50,37.7 50,36.94 49.24,36.18 39.33,36.18 38.57,36.94 38.57,39.23 IC6.18
N$8
  Top 0.4: IC4.13 49.49,16.11 49.49,31.35
  Top 0.406: IC1.32 41.11,45.58 36.16,40.62 IC6.19 36.16,36.81 37.05,35.93 48.73,35.93 49.49,35.16 49.49,31.35 | 49.49,16.11 49.75,15.86 49.75,13.57 49.24,13.07 42.63,13.07 42.13,12.56 42.13,10.78 40.6,9.26 40.6,5.7 39.84,4.94 34,4.94 33.36,5.57 IC5.9
N$9
  Top 0.406: U$4.P$1 IC6.10 36.03,23.99 36.03,20.18 33.36,17.51 IC5.12
N$10
  Top 0.406: U$5.P$1 IC6.9 33.49,23.99 33.49,20.18 30.82,17.51 IC5.13
N$11
  Top 0.406: U$6.P$1 IC6.8 30.95,23.99 30.95,20.18 28.28,17.51 IC5.14
N$12
  Top 0.406: U$12.P$1 IC6.7 28.41,23.99 28.41,20.18 25.74,17.51 IC5.15
N$13
  Top 0.406: U$14.P$1 IC6.6 25.87,23.99 25.87,20.18 23.2,17.51 IC5.16
N$14
  Top 0.406: U$7.P$1 IC6.5 23.33,23.99 23.33,20.18 20.66,17.51 IC5.17
N$15
  Top 0.406: U$9.P$1 IC6.4 20.79,23.99 20.79,20.18 18.12,17.51 IC5.18
N$16  (via drill 0.61)
  Top 0.4: 9.36,24.24 9.36,37.96 8.6,38.72 8.6,44.82 9.61,45.83 v9.61,47.61
  Top 0.406: U$10.P$1 IC6.3 18.25,23.99 18.25,22.21 17.23,21.19 12.41,21.19 9.36,24.24
  Bottom 0.406: v9.61,47.61 IC1.21
N$17  (via drill 0.61)
  Top 0.406: IC6.25 21.04,39.48 21.04,41.01 20.51,41.54 v17.74,41.54 | v15.2,41.54 15.2,42.28 15.71,42.78 15.71,44.82 15.46,45.07 15.46,45.83 15.71,46.09 IC1.22
  Bottom 0.4: v15.2,41.54 v17.74,41.54
N$18
  Top 0.406: IC6.24 23.46,44.44 22.57,45.32 18.76,45.32 18.25,45.83 IC1.23
N$19  (via drill 0.61)
  Top 0.4: 29.17,43.04 29.17,43.55 v29.17,45.32
  Top 0.406: IC6.21 31.08,40.62 29.17,42.53 29.17,43.55
  Bottom 0.4: v29.17,45.32 21.55,45.32 20.79,46.09 IC1.24
N$20
  Top 0.406: IC6.23 26,40.88 25.62,41.26 25.62,45.07 25.11,45.58 23.84,45.58 23.33,46.09 IC1.25
N$21
  Top 0.4: 25.36,47.86 IC1.26
  Top 0.406: 25.36,47.86 25.36,48.12 21.43,52.05 18.88,52.05 16.22,54.72 14.06,54.72 12.79,53.45 12.79,51.8 10.88,49.9 10.88,45.83 9.87,44.82 9.87,38.97 10.38,38.47 10.38,34.78 11.52,33.64 11.52,23.35 12.66,22.21 15.2,22.21 15.71,22.72 15.71,23.99 IC6.2 U$3.P$1
N$22  (via drill 0.61)
  Top 0.4: 27.9,42.78 27.9,46.59 IC1.27
  Top 0.406: 27.9,42.78 27.9,42.02 v27.39,41.51
  Bottom 0.4: v27.39,41.51 20.28,41.51 19.01,40.24 IC6.26
N$23  (via drill 0.61)
  Top 0.4: 11.39,35.16 11.39,38.72 10.88,39.23 10.88,44.56 11.9,45.58 11.9,49.64 v15.2,52.94
  Top 0.406: IC6.1 U$2.P$1 13.3,33.26 11.39,35.16
  Bottom 0.406: v15.2,52.94 29.93,52.94 30.95,51.93 IC1.28
N$24  (via drill 0.61)
  Top 0.406: v19.01,54.47 19.01,55.48 19.27,55.74 22.57,55.74 23.33,56.5 IC1.16 | v7.07,52.94 7.07,51.42 6.31,50.66 6.31,47.1 v5.55,46.34 | v16.98,45.32 16.98,42.53 16.47,42.02 16.47,39.99 IC6.27
  Bottom 0.4: 8.85,45.32 v16.98,45.32
  Bottom 0.406: v19.01,54.47 13.93,54.47 12.41,52.94 v7.07,52.94 | 8.85,45.32 6.57,45.32 v5.55,46.34
N$25  (via drill 0.61)
  Top 0.4: v63.46,32.62 63.46,49.13 v62.19,50.4
  Top 0.406: IC2.5 39.59,71.23 38.06,69.71 38.06,67.68 36.28,65.9 v30.44,65.9
  Bottom 0.4: 32.98,35.16 52.03,35.16 54.57,32.62 v63.46,32.62
  Bottom 0.406: 33.87,59.8 22.31,59.8 | 33.87,59.8 35.52,58.15 35.52,52.94 36.41,52.05 | 36.41,52.05 36.79,51.67 | 20.79,62.6 20.79,61.33 | 20.79,62.6 IC1.17 | v62.19,50.4 61.94,50.4 61.56,50.78 37.68,50.78 36.41,52.05 | 33.87,59.8 22.06,59.8 20.79,61.07 20.79,62.6 | 20.79,62.6 20.79,64.63 21.3,65.14 29.68,65.14 v30.44,65.9 | 32.98,35.16 29.17,35.16 28.54,35.8 IC6.22
N$26
  Top 0.406: IC3.8 62.45,69.45 61.68,70.22 61.68,78.85 62.45,79.61 IC3.12
N$27  (via drill 0.61)
  Top 0.4: v41.87,3.41 41.87,7.22 IC4.1 | v64.73,3.41 66,4.68 | 68.03,37.96 68.03,71.23 v67.27,71.99
  Top 0.406: 68.03,37.96 68.03,36.94 67.27,36.18 67.27,34.15 67.78,33.64 67.78,20.94 66.76,19.92 66.76,17.64 67.78,16.62 67.78,6.46 66,4.68
  Bottom 0.4: v41.87,3.41 v64.73,3.41 | v67.27,71.99 IC3.9
N$28
  Top 0.4: IC3.6 55.84,71.99 | 55.84,82.15 IC3.2
  Top 0.406: 55.84,82.15 54.83,82.15 54.32,81.65 54.32,72.76 55.08,71.99 IC3.6
N$29
  Top 0.4: IC3.13 63.46,82.15
  Top 0.406: IC3.13 62.07,82.15 60.92,83.3 60.92,85.2 60.16,85.96 45.94,85.96 45.43,85.46 41.87,85.46 40.86,84.44 40.86,76.82 39.84,75.8 29.68,75.8 29.43,75.55 IC2.1
N$31  (via drill 0.61)
  Top 0.406: IC2.6 42.13,71.74 41.24,70.85 40.6,70.85 39.21,69.45 39.21,67.04 38.57,66.41 v38.57,65.39
  Bottom 0.4: 31.97,65.39 v38.57,65.39
  Bottom 0.406: IC1.13 30.95,64.37 31.97,65.39
N$32
  Top 0.406: IC1.18 18.25,67.17 19.77,68.69 20.35,68.69 Q1.2
  Bottom 0.406: Q1.2 22.63,69.07 C8.2
N$33
  Top 0.406: IC1.19 15.71,68.88 Q1.1
  Bottom 0.406: C9.2 15.39,68.56 Q1.1
N$34
  Bottom 0.406: R13.1 33.61,71.36 33.24,71.74 33.24,75.04 35.01,76.82 35.01,78.09 35.78,78.85 37.05,78.85 37.81,78.09 47.49,78.09 47.74,78.34 | 47.71,80.3 S1.2 47.74,78.34 | 47.74,78.34 S1.1
N$35  (via drill 0.61)
  Top 0.4: v72.35,56.75 72.35,65.64 76.16,69.45 R7.2
  Top 0.406: v40.6,52.94 39.08,52.94 38.57,52.44 IC1.31 | v72.35,56.75 72.35,38.97 72.86,38.47 73.84,38.47 X1.11
  Bottom 0.4: v40.6,52.94 39.33,52.94 R2.2
  Bottom 0.406: v40.6,52.94 40.86,53.2 40.86,59.04 41.62,59.8 70.83,59.8 72.35,58.28 v72.35,56.75
N$36  (via drill 0.61)
  Top 0.4: IC2.2 31.71,73.26
  Top 0.406: IC2.3 34.51,71.61 33.62,70.72 31.97,70.72 | X1.2 75.89,49.66 75.27,50.28 75.27,61.33 v74.89,61.71 | IC1.15 25.87,69.2 27.39,70.72 31.97,70.72 | 31.97,70.72 IC2.2
  Bottom 0.406: IC2.3 34.51,71.99 35.27,71.23 49.75,71.23 50.25,70.72 50.25,67.93 68.8,67.93 69.56,67.17 69.56,63.1 70.95,61.71 v74.89,61.71
N$37  (via drill 0.61)
  Top 0.406: v9.61,17.51 9.23,17.89 9.23,18.65 5.8,22.08 2.76,22.08 1.87,22.97 1.87,42.66 v3.01,43.8 | v31.71,42.78 31.71,44.56 32.47,45.32 35.27,45.32 36.03,46.09 IC1.30
  Bottom 0.406: v3.01,43.8 4.03,42.78 v31.71,42.78 | IC5.11 35.9,17 35.01,17.89 9.99,17.89 v9.61,17.51
N$38  (via drill 0.61)
  Top 0.406: v71.34,68.44 70.57,67.68 70.57,50.15 71.34,49.39 71.34,47.1 70.32,46.09 70.32,36.69 70.57,36.43 v71.08,36.43
  Bottom 0.4: v71.08,36.43 74.89,36.43 76.16,37.7 X1.12 | 66,73.26 59.14,73.26 57.87,74.53 IC3.5
  Bottom 0.406: 66,73.26 v67.27,74.53 68.03,74.53 71.08,71.49 71.08,68.69 v71.34,68.44
N$39  (via drill 0.61)
  Top 0.4: 69.56,74.79 69.56,50.91
  Top 0.406: 69.56,50.91 v69.56,48.37 | 69.56,74.79 67.27,77.07 IC3.11 | v38.57,84.19 38.32,83.93 38.32,79.61 v36.28,77.58
  Bottom 0.4: 59.65,78.34 60.92,77.07 IC3.11
  Bottom 0.406: 59.65,78.34 54.83,78.34 54.32,78.85 54.32,83.68 53.56,84.44 38.82,84.44 v38.57,84.19 | v36.28,77.58 36.28,76.57 37.05,75.8 IC2.4 | X1.3 72.53,46.41 70.57,48.37 v69.56,48.37
N$40  (via drill 0.61)
  Top 0.4: v58.38,40.24 58.38,37.7 57.11,36.43 R9.1
  Bottom 0.406: v58.38,40.24 59.78,41.64 73.12,41.64 X1.7
N$41  (via drill 0.61)
  Top 0.406: X1.8 76.04,41.26 76.67,41.26 77.18,40.75 77.18,35.93 75.15,33.89 v74.13,33.89
  Bottom 0.4: v74.13,33.89 54.57,33.89 52.03,36.43 R10.1
N$42  (via drill 0.61)
  Top 0.4: v60.92,37.7 60.92,22.97 59.91,21.7 IC4.9
  Bottom 0.4: v60.92,37.7 63.46,40.24
  Bottom 0.406: 63.46,40.24 63.97,40.75 72.86,40.75 73.2,40.41 X1.9
N$43  (via drill 0.61)
  Top 0.406: v71.08,28.81 69.81,27.54 69.81,19.16 v69.3,18.65
  Bottom 0.4: 54.57,18.65 v69.3,18.65
  Bottom 0.406: v71.08,28.81 71.08,31.1 72.1,32.12 76.16,32.12 77.43,33.39 77.43,38.97 76.92,39.48 75.96,39.48 X1.10 | IC4.12 52.29,17.64 53.3,18.65 54.57,18.65
N$45
  Bottom 0.4: C14.1 29.17,93.58 29.17,96.12 IC8.3
N$48
  Top 0.4: R4.1 16.47,96.12 | IC8.5 26.63,89.77 21.55,89.77 21.55,92.31 R5.2
  Top 0.406: 16.47,96.12 18.5,96.12 19.01,95.62 19.01,93.33 19.52,92.82 21.17,92.82 R5.2
N$49
  Top 0.4: K1.1 71.08,75.8
  Top 0.406: R7.1 71.72,70.34 71.08,70.98 K1.1
N$50
  Top 0.4: R11.2 11.39,96.12
  Top 0.406: LED1.A 8.6,94.85 9.87,96.12 11.71,96.12 R11.2
N$51  (via drill 0.61)
  Top 0.4: 11.39,81.9 16.47,86.98 R4.2
  Top 0.406: v13.68,58.02 12.66,58.02 11.39,59.29 11.39,81.9
  Bottom 0.406: v13.68,58.02 14.69,57.01 20.79,57.01 23.84,53.96 32.73,53.96 R1.1
N$52
  Bottom 0.406: IC1.29 33.49,50.4 R1.2
N$53
  Top 0.4: R6.2 39.33,89.77 34.25,89.77 IC8.8
N$54  (via drill 0.61)
  Top 0.4: v44.41,87.23 39.33,87.23 R6.1 | R8.1 54.57,91.04 54.57,94.85 Q2.2
  Bottom 0.4: v44.41,87.23 48.22,91.04 52.03,91.04 54.57,93.58 54.57,94.85 Q2.2
N$55
  Top 0.4: R8.2 52.03,91.04 53.3,92.31 53.3,93.58 Q2.1
  Top 0.406: IC8.7 31.97,86.03 R3.1
  Bottom 0.4: 41.87,87.23 32.73,87.23 31.97,88 IC8.7
  Bottom 0.406: 41.87,87.23 42.13,87.23 43.65,88.76 44.67,88.76 47.97,92.06 51.91,92.06 53.11,93.27 Q2.1
N$57
  Top 0.6: JP1.1 72.35,87.23
  Top 0.61: K1.6 71.08,83.42 | K1.6 71.08,86.98 71.59,87.49 72.54,87.49 JP1.1 | K1.6 71.08,79.61 72.61,78.09 76.67,78.09 78.19,76.57 78.19,44.82 77.18,43.8 76.28,43.8 X1.6
N$58  (via drill 0.61)
  Top 0.406: IC4.4 49.75,10.78 51.27,12.3 v53.3,12.3
  Bottom 0.4: v53.3,12.3 54.57,13.57 66,13.57 | R9.2 57.11,26.27
  Bottom 0.406: 54.57,13.57 69.81,13.57 71.72,15.48 71.72,22.97 68.8,25.89 64.35,25.89 63.46,26.78 57.3,26.78 R9.2
N$59  (via drill 0.61)
  Top 0.4: v63.46,25 63.46,2.14 57.11,2.14 57.11,7.22 IC4.7
  Bottom 0.4: v63.46,25 53.3,25 52.03,26.27 R10.2
N$60
  Top 0.61: D4.A 4.15,81.27 5.55,79.87 5.55,77.48 X2.1
N$61  (via drill 0.61)
  Top 0.406: v73.62,59.29 73.88,59.29 74.38,58.79 74.38,48.9 X1.1
  Bottom 0.4: 29.17,60.82 34.51,60.82 | v73.62,59.29 76.16,59.29 77.43,60.56 77.43,66.91 66,78.34 60.92,78.34 59.65,79.61 IC3.3
  Bottom 0.406: 29.17,60.82 28.41,61.58 IC1.14 | 34.51,60.82 71.08,60.82 72.61,59.29 v73.62,59.29
N$63  (via drill 0.61)
  Top 0.4: v11.39,56.75 8.85,54.21 8.85,51.67 7.33,50.15 7.33,46.09 6.31,45.07 6.31,31.35
  Top 0.406: 6.31,31.35 6.31,30.72 5.42,29.83 SV3.1 | v21.3,54.47 22.82,54.47 24.35,55.99 24.35,60.31 24.85,60.82 33.24,60.82 33.49,61.07 IC1.12
  Bottom 0.406: v11.39,56.75 11.39,55.99 11.9,55.48 17.74,55.48 18.25,55.99 20.28,55.99 21.3,54.98 v21.3,54.47
PB0
  Bottom 0.406: IC1.1 SV1.3
PB1
  Bottom 0.406: IC1.2 SV1.4
PB2
  Bottom 0.406: IC1.3 SV1.5
PB3
  Bottom 0.406: IC1.4 SV1.6
PB4
  Bottom 0.406: IC1.5 SV1.7
RESET  (via drill 0.61)
  Top 0.4: 2.5,59.29 SV2.5 5.04,59.29
  Top 0.406: v10.12,70.72 10.12,68.06 8.34,66.28 8.34,60.31 7.33,59.29 SV2.5 | 2.5,59.29 1.74,58.53 1.74,47.36 4.28,44.82 4.28,41.51 4.03,41.26 SV3.5 | v41.36,68.82 41.11,68.56 IC1.9
  Bottom 0.406: v10.12,70.72 10.12,71.74 11.14,72.76 22.82,72.76 | 22.82,72.76 26.89,72.76 28.92,70.72 30.7,70.72 31.46,69.96 31.46,68.18 31.97,67.68 36.54,67.68 | C10.2 42.13,69.58 v41.36,68.82 40.22,67.68 36.54,67.68 | R13.2 36.41,67.8 36.54,67.68 | R12.2 22.69,72.89 22.82,72.76
RXD  (via drill 0.61)
  Top 0.4: v62.19,52.94 64.73,50.4 v64.73,47.86
  Top 0.406: IC1.10 38.57,60.31 39.08,59.8 42.13,59.8 42.89,59.04 v42.89,57.01 | v14.44,44.05 14.44,43.29 13.68,42.53 v13.7,41.54
  Bottom 0.4: v14.44,44.05 60.92,44.05 | 6.31,39.23 6.31,37.96 5.8,37.45 SV3.4
  Bottom 0.406: 60.92,44.05 63.59,44.05 64.73,45.2 v64.73,47.86 | v42.89,57.01 42.89,58.02 43.65,58.79 61.43,58.79 62.19,58.02 v62.19,52.94 | v13.7,41.54 7.1,41.54 6.31,40.75 6.31,39.23
SCK  (via drill 0.61)
  Top 0.406: IC1.8 43.65,59.55 44.16,59.04 44.16,55.99 43.65,55.48 34.76,55.48 34.25,55.99 v32.98,55.99
  Bottom 0.406: IC1.8 SV1.10 | SV2.4 9.36,56.75 12.15,59.55 14.44,59.55 15.96,58.02 21.55,58.02 22.31,58.79 32.47,58.79 32.98,58.28 v32.98,55.99
TXD  (via drill 0.61)
  Top 0.4: v9.61,50.4 8.34,49.13 8.34,45.83 7.58,45.07 v7.58,37.7
  Top 0.406: v25.36,50.4 25.36,59.29 25.87,59.8 35.01,59.8 36.03,60.82 IC1.11
  Bottom 0.4: v9.61,50.4 v25.36,50.4 | v7.58,37.7 6.31,36.43 6.31,35.42 5.8,34.91 SV3.3
VIN  (via drill 0.8 pad 1.93)
  Bottom 0.813: IC7.IN 18.06,76.38 17.49,75.8 12.92,75.8 D2.C 9.93,75.74 9.11,76.82 9.11,82.66 | 9.11,82.66 9.11,86.47 8.6,86.98 C11.+ v6.06,88.12 | 9.11,82.66 D4.C
VOUT  (via drill 0.8 pad 1.93)
  Top 0.6: R5.1 21.55,96.12 26.63,96.12 IC8.4 | 76.16,83.42 K1.4 | 74.89,87.23 JP1.2 74.89,88.5 71.08,92.31 C16.-
  Top 0.61: 76.16,83.42 76.16,86.98 75.65,87.49 75.21,87.49 JP1.2
  Bottom 0.6: 26.63,93.58 26.63,96.12 IC8.4 | 26.63,93.58 28.16,92.06 40.86,92.06 | 26.63,93.58 C14.2
  Bottom 0.61: 40.86,92.06 42.13,90.79 45.05,90.79 D1.A 48.35,93.71 51.27,96.63 51.27,97.14 52.29,98.16 54.83,98.16 57.37,95.62 68.03,95.62 69.05,94.6 v70.83,94.6 70.83,92.25 C16.-

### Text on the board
tNames: GND | Reset | SCK | MISO | MOSI | 1 | Reset | RXD | TXD | FRAME | GND | LOAD | RTS | CP | +5V | GND | -VEE | D0 | D1 | D3 | D4 | D. OFF | M AC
